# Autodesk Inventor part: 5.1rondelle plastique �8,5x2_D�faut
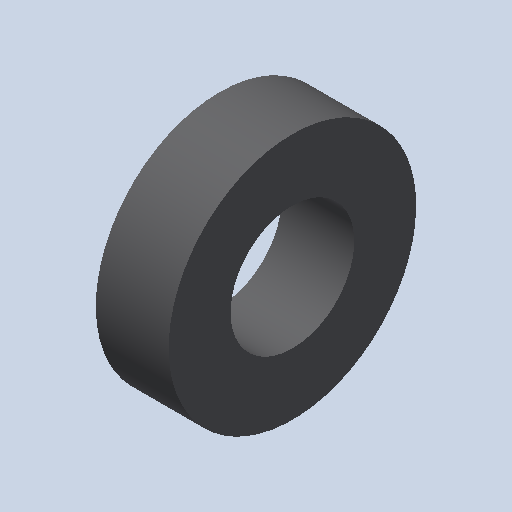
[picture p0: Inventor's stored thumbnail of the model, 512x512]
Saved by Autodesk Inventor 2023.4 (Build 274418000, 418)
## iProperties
Created: 2011-01
Part Number: 5.1rondelle plastique �8,5x2_D�faut
Document SubType Name: Modeling
Designer: eric
Density: 1 g/cm^3
Mass: 0.851175 g
Surface Area: 7.41023 cm^2
Volume: 0.851175 cm^3
Material: Générique
Appearance: Red
Author: eric
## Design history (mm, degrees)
feature "Base1"
node "Corps solides"
node "Corps surfaciques"
node "Solide1"
